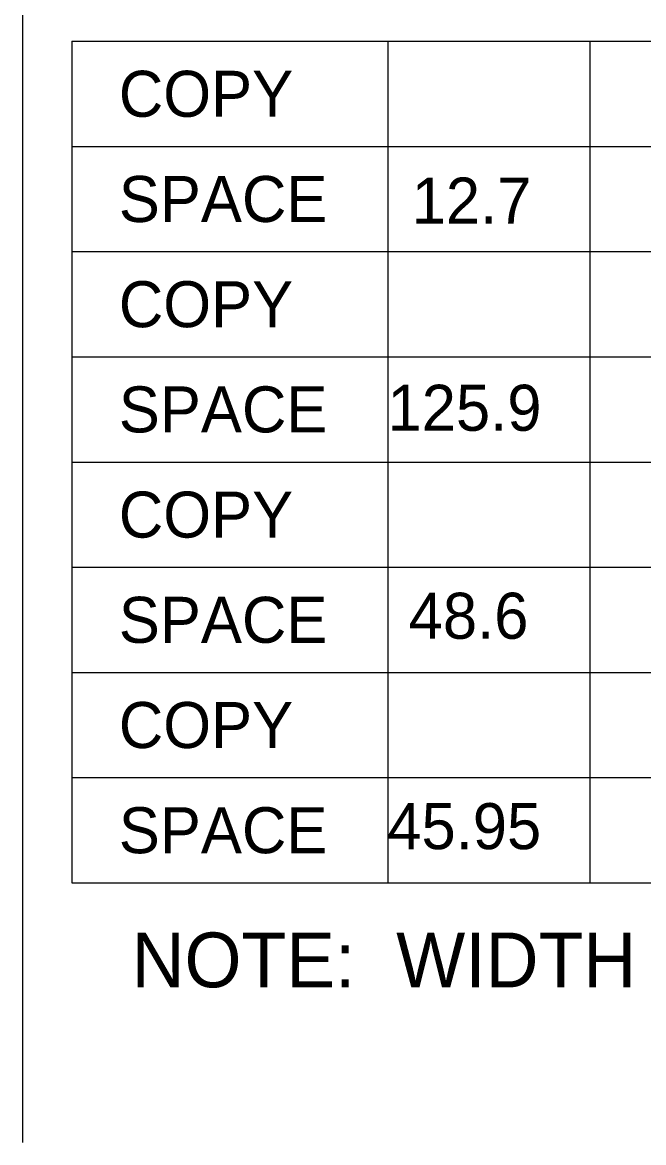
# Model space of a CAD drawing. Extents: x 10268312 to 10268472, y 2142583 to 2142688.
# Drawn here: x 10268394.73 to 10268404.18, y 2142592.28 to 2142609.32 of the extents above; entities that cross this region are included whole.
import ezdxf

# ---------------------------------------------------------------- set-up
doc = ezdxf.new("R2010")
doc.units = 0
for name, color, linetype in [('SheetBorder_dp', 7, 'Continuous'), ('SumBoxLines_dp', 7, 'Continuous'), ('SumBoxLinesMin_dp', 7, 'Continuous'), ('TextLabel', 7, 'Continuous'), ('TextMisc', 7, 'Continuous'), ('TextNotes', 7, 'Continuous')]:
    doc.layers.add(name, color=color, linetype=linetype)

msp = doc.modelspace()

# ---------------------------------------------------------------- linework, layer by layer
at = {"layer": 'SheetBorder_dp'}
msp.add_line((10268394.73, 2142688.282), (10268394.73, 2142592.282), dxfattribs=at)
at = {"layer": 'SumBoxLines_dp'}
for p, q in [((10268395.48, 2142609.032), (10268470.98, 2142609.032)), ((10268395.48, 2142609.032), (10268470.98, 2142609.032)), ((10268395.48, 2142609.032), (10268395.48, 2142596.232)), ((10268400.289, 2142609.032), (10268400.289, 2142596.232)), ((10268403.363, 2142609.032), (10268403.363, 2142596.232)), ((10268403.363, 2142609.032), (10268403.363, 2142604.232)), ((10268395.48, 2142605.832), (10268470.98, 2142605.832)), ((10268395.48, 2142602.632), (10268470.98, 2142602.632)), ((10268395.48, 2142599.432), (10268470.98, 2142599.432)), ((10268395.48, 2142596.232), (10268470.98, 2142596.232))]:
    msp.add_line(p, q, dxfattribs=at)
at = {"layer": 'SumBoxLinesMin_dp'}
for p, q in [((10268395.48, 2142607.432), (10268470.98, 2142607.432)), ((10268395.48, 2142604.232), (10268470.98, 2142604.232)), ((10268395.48, 2142601.032), (10268470.98, 2142601.032)), ((10268395.48, 2142597.832), (10268470.98, 2142597.832))]:
    msp.add_line(p, q, dxfattribs=at)

# ---------------------------------------------------------------- texts
at = {"layer": 'TextLabel'}
for s, p in [('12.7', (10268400.652, 2142606.258)), ('125.9', (10268400.285, 2142603.107)), ('48.6', (10268400.607, 2142599.944)), ('45.95', (10268400.281, 2142596.744))]:
    msp.add_text(s, height=0.7, dxfattribs=at).set_placement(p)
at = {"layer": 'TextMisc'}
for s, p in [('COPY', (10268396.197, 2142607.882)), ('SPACE', (10268396.197, 2142606.282)), ('COPY', (10268396.197, 2142604.682)), ('SPACE', (10268396.197, 2142603.082)), ('COPY', (10268396.197, 2142601.482)), ('SPACE', (10268396.197, 2142599.882)), ('COPY', (10268396.197, 2142598.282)), ('SPACE', (10268396.197, 2142596.682))]:
    msp.add_text(s, height=0.7, dxfattribs=at).set_placement(p)
at = {"layer": 'TextNotes'}
msp.add_text('NOTE:  WIDTH - HORIZONTAL SPACING DIMENSIONS ARE IN INCHES.', height=0.83333, dxfattribs=at).set_placement((10268396.392, 2142594.643))

doc.saveas('drawing.dxf')
